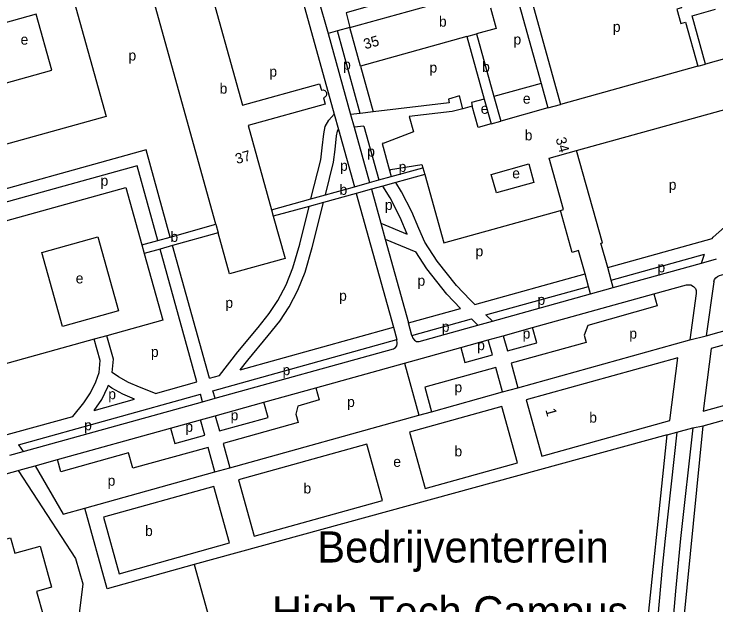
# Model space of a CAD drawing. Extents: x 158358 to 160383, y 379531 to 380764.
# Drawn here: x 159753.6 to 160024.2, y 380106.3 to 380334.2 of the extents above; entities that cross this region are included whole.
import ezdxf

# ---------------------------------------------------------------- set-up
doc = ezdxf.new("R2010")
doc.units = 0
for name, color, linetype in [('BLT_Basislijn', 7, 'Continuous'), ('BLT_Bebouwing', 7, 'Continuous'), ('BLT_Centroide', 7, 'Continuous'), ('BLT_Huisnummer', 7, 'Continuous'), ('BLT_Huisnummer_reeks', 7, 'Continuous'), ('BLT_Onderverdeling_panden', 7, 'Continuous'), ('BLT_Sport_parknaam', 7, 'Continuous')]:
    doc.layers.add(name, color=color, linetype=linetype)

msp = doc.modelspace()

# ---------------------------------------------------------------- linework, layer by layer
at = {"layer": 'BLT_Basislijn'}
for p, q in [((159931.55, 380417.09), (159964.23, 380299.3)), ((159943.9, 380353.87), (159956.78, 380307.42)), ((159887.16, 380314.11), (159892.07, 380296.44)), ((159956.78, 380307.42), (159959.41, 380297.96)), ((159898.37, 380273.85), (159899.01, 380271.52)), ((159894.97, 380253.48), (159905.09, 380249.26)), ((159896.67, 380247.35), (159908.43, 380242.45)), ((159982.44, 380236.4), (160022.76, 380247.6)), ((159983.78, 380231.58), (160019.71, 380241.57)), ((159931.28, 380222.18), (159973.73, 380233.97)), ((159935.51, 380218.16), (159975.06, 380229.16)), ((159953.5, 380213.3), (160000.19, 380226.28)), ((159905.65, 380215.05), (159925.68, 380220.62)), ((159906.99, 380210.23), (159905.65, 380215.05)), ((159906.99, 380210.23), (159929.89, 380216.6)), ((159840.8, 380197.03), (159899.87, 380213.45)), ((159899.87, 380213.45), (159901.21, 380208.63)), ((159942.17, 380210.15), (159953.5, 380213.3)), ((159942.17, 380210.15), (159943.82, 380204.33)), ((160014.1, 380208.5), (160020.43, 380210.12)), ((159830.24, 380188.9), (159901.21, 380208.63)), ((159925.81, 380205.6), (159936.4, 380208.55)), ((159937.99, 380202.72), (159936.4, 380208.55)), ((159904.12, 380199.58), (159925.81, 380205.6)), ((159869.86, 380190.05), (159904.12, 380199.58)), ((159904.12, 380199.58), (159909.69, 380179.49)), ((159945.19, 380199.52), (159947.86, 380190.08)), ((159939.31, 380197.89), (159911.89, 380190.28)), ((159941.9, 380188.45), (159939.31, 380197.89)), ((159828.91, 380193.72), (159832.72, 380194.78)), ((159808.05, 380187.92), (159824.09, 380192.38)), ((159849.91, 380184.51), (159869.86, 380190.05)), ((159911.89, 380190.28), (159914.51, 380180.83)), ((159941.9, 380188.45), (159947.86, 380190.08)), ((159755.26, 380168.06), (159825.43, 380187.56)), ((159914.51, 380180.83), (159941.9, 380188.45)), ((159784.47, 380181.37), (159799.95, 380185.67)), ((159831.17, 380179.3), (159849.91, 380184.51)), ((159831.17, 380179.3), (159832.81, 380173.46)), ((159836.8, 380159.21), (159909.69, 380179.49)), ((159909.69, 380179.49), (159914.51, 380180.83)), ((159700.92, 380158.15), (159776.17, 380179.06)), ((159813.89, 380174.49), (159825.45, 380177.71)), ((159827.08, 380171.84), (159825.45, 380177.71)), ((159770.26, 380162.37), (159813.89, 380174.49)), ((160009.06, 380172.98), (160015.33, 380174.69)), ((160015.33, 380174.69), (160019.2, 380175.38)), ((160005.42, 380171.89), (160009.06, 380172.98)), ((159834.16, 380168.65), (159836.8, 380159.21)), ((159755.26, 380168.06), (159757.09, 380165.46)), ((159831.02, 380157.61), (159828.41, 380167.02)), ((159761.71, 380159.99), (159770.26, 380162.37)), ((159831.02, 380157.61), (159836.8, 380159.21))]:
    msp.add_line(p, q, dxfattribs=at)
for points in [[(159894.88, 380347.44), (159897.28, 380339.12), (159881.55, 380334.6), (159883.03, 380328.99)], [(159864.4, 380341.04), (159877.04, 380295.57)], [(159870.73, 380340.69), (159874.63, 380326.66)], [(159883.03, 380328.99), (159878.21, 380327.65)], [(159878.21, 380327.65), (159874.63, 380326.66)], [(159874.63, 380326.66), (159883.32, 380295.38)], [(159887.05, 380295.83), (159878.21, 380327.65)], [(159956.78, 380307.42), (159938.6, 380302.42)], [(159926.61, 380297.67), (159925.35, 380302.58), (159921.12, 380301.39), (159921.36, 380299.97), (159892.07, 380296.44)], [(159934.86, 380301.39), (159929.88, 380300.02), (159930.25, 380298.67)], [(159868.05, 380262.93), (159871.79, 380277.92), (159872.4, 380282.55), (159872.96, 380288.04), (159873.57, 380290.78), (159874.93, 380293.24), (159877.04, 380295.57)], [(159877.04, 380295.57), (159878.68, 380289.68)], [(159887.05, 380295.83), (159883.32, 380295.38)], [(159892.07, 380296.44), (159887.05, 380295.83)], [(159883.32, 380295.38), (159884.68, 380290.51)], [(159888.45, 380290.96), (159884.68, 380290.51)], [(159884.68, 380290.51), (159890.6, 380269.19)], [(159888.45, 380290.96), (159894.2, 380270.18)], [(159873.59, 380264.47), (159876.71, 380276.99), (159877.37, 380281.97), (159877.9, 380287.23), (159878.3, 380288.99), (159878.68, 380289.68)], [(159878.68, 380289.68), (159884.82, 380267.58)], [(160022.76, 380247.6), (160023.14, 380248.08), (160029.71, 380253.93), (160036.19, 380260.62), (160054.43, 380283.44)], [(159813.81, 380248.2), (159804.49, 380281.82), (159728.62, 380260.79)], [(159982.44, 380236.4), (159979.84, 380245.78), (159980.38, 380245.93), (159970.47, 380281.52)], [(159809, 380246.85), (159801.01, 380275.67), (159729.96, 380255.97)], [(159931.28, 380222.18), (159929.36, 380224), (159924.16, 380229.47), (159916.72, 380238.89), (159911.99, 380246.15), (159909.59, 380251.47), (159906.97, 380257.87), (159902.92, 380265.67), (159900.8, 380269.23)], [(159891.32, 380266.62), (159894.97, 380253.48)], [(159905.09, 380249.26), (159902.43, 380255.77), (159898.54, 380263.24), (159895.81, 380267.86)], [(159885.53, 380265.03), (159899.87, 380213.45)], [(159840.8, 380197.03), (159843.71, 380200.77), (159851.51, 380210.18), (159856.03, 380215.77), (159859.6, 380221.24), (159862.98, 380227.71), (159865.79, 380234.65), (159868.53, 380244.18), (159872.86, 380261.54)], [(159832.72, 380194.78), (159839.81, 380203.9), (159847.64, 380213.35), (159851.99, 380218.72), (159855.28, 380223.77), (159858.44, 380229.81), (159861.05, 380236.28), (159863.7, 380245.48), (159867.33, 380260.02)], [(159973.73, 380233.97), (159971.23, 380242.96), (159968.71, 380242.26), (159964.23, 380258.45)], [(159894.97, 380253.48), (159896.67, 380247.35)], [(159896.67, 380247.35), (159905.65, 380215.05)], [(159828.91, 380193.72), (159814.72, 380244.92)], [(159824.09, 380192.38), (159809.91, 380243.57)], [(159925.68, 380220.62), (159920.38, 380226.19), (159912.66, 380235.97), (159908.43, 380242.45)], [(160018.59, 380238.14), (160019.71, 380241.57)], [(160018.59, 380238.14), (160024.38, 380239.75)], [(159983.78, 380231.58), (159982.44, 380236.4)], [(159984.58, 380228.69), (160018.59, 380238.14)], [(159975.06, 380229.16), (159973.73, 380233.97)], [(160023.36, 380230.91), (160023.63, 380231.76), (160024.09, 380232.43), (160024.73, 380232.98), (160025.52, 380233.33), (160029.14, 380234.33)], [(159984.58, 380228.69), (159983.78, 380231.58)], [(160023.36, 380230.91), (160020.43, 380210.12)], [(159975.87, 380226.27), (159975.06, 380229.16)], [(159975.87, 380226.27), (159984.58, 380228.69)], [(160000.19, 380226.28), (160012.79, 380229.78), (160014.47, 380229.82), (160015.59, 380229.13), (160016.28, 380228.29), (160016.55, 380227.52), (160016.55, 380226.41)], [(159938.05, 380215.75), (159975.87, 380226.27)], [(160000.19, 380226.28), (160001.47, 380221.65), (159974.82, 380214.12), (159973.35, 380210.4), (159974.15, 380207.57), (159945.19, 380199.52)], [(160016.55, 380226.41), (160014.1, 380208.5)], [(160020.43, 380210.12), (160058.15, 380220.73)], [(159938.05, 380215.75), (159935.51, 380218.16)], [(159932.43, 380214.19), (159929.89, 380216.6)], [(159932.43, 380214.19), (159938.05, 380215.75)], [(159906.99, 380210.23), (159907.37, 380209.23), (159907.91, 380208.44), (159908.77, 380207.95), (159909.7, 380207.87), (159932.43, 380214.19)], [(159943.82, 380204.33), (159955.1, 380207.46), (159953.5, 380213.3)], [(159791.36, 380195.9), (159791.87, 380201.04), (159789.32, 380210.16)], [(159936.4, 380208.55), (159942.17, 380210.15)], [(159776.17, 380179.06), (159780.44, 380184.33), (159783.03, 380188.11), (159785.07, 380192.34), (159786.35, 380195.97), (159786.8, 380200.6), (159784.5, 380208.82)], [(159831.05, 380186.01), (159899.89, 380205.15), (159900.67, 380205.65), (159901.09, 380206.24), (159901.32, 380207.11), (159901.21, 380208.63)], [(159947.86, 380190.08), (160014.1, 380208.5)], [(159925.81, 380205.6), (159927.42, 380199.78), (159937.99, 380202.72)], [(159808.05, 380187.92), (159801.94, 380190.26), (159797.73, 380192.05), (159793.9, 380194.25), (159791.36, 380195.9)], [(159784.47, 380181.37), (159787.37, 380185.6), (159789.69, 380190.42), (159789.87, 380190.91)], [(159799.95, 380185.67), (159795.5, 380187.56), (159791.29, 380189.98), (159789.87, 380190.91)], [(159869.86, 380190.05), (159871.15, 380185.39), (159862.98, 380183), (159862.27, 380179.89), (159863.15, 380176.71), (159834.16, 380168.65)], [(160019.2, 380175.38), (160073.01, 380190.33)], [(159826.23, 380184.67), (159825.43, 380187.56)], [(159831.05, 380186.01), (159830.24, 380188.9)], [(159757.09, 380165.46), (159826.23, 380184.67)], [(159826.23, 380184.67), (159831.05, 380186.01)], [(159832.81, 380173.46), (159851.53, 380178.67), (159849.91, 380184.51)], [(159825.45, 380177.71), (159831.17, 380179.3)], [(159813.89, 380174.49), (159815.5, 380168.65), (159827.08, 380171.84)], [(160015.33, 380174.69), (160010.57, 380131.9), (160008.55, 380111.65), (160007.13, 380095.3)], [(160010.67, 380088.45), (160019.2, 380175.38)], [(160005.42, 380171.89), (159823.01, 380121.88)], [(159996.53, 380086.65), (160005.42, 380171.89)], [(160009.06, 380172.98), (160004.59, 380131.94), (160003.46, 380120.81), (160001.19, 380094.85)], [(159828.41, 380167.02), (159799.39, 380159.02), (159797.74, 380165.02), (159771.55, 380157.68), (159770.26, 380162.37)], [(159751.98, 380164.03), (159757.09, 380165.46)], [(159725.52, 380149.93), (159755.15, 380158.17)], [(159755.15, 380158.17), (159755.48, 380158.26), (159758.37, 380159.06), (159761.71, 380159.99)], [(159755.15, 380158.17), (159777.32, 380124.26), (159780.09, 380114.47), (159775.39, 380076.25)], [(159761.71, 380159.99), (159772.55, 380141.36), (159780.81, 380143.65)], [(159780.81, 380143.65), (159831.02, 380157.61)], [(159823.01, 380121.88), (159789.45, 380112.55), (159780.81, 380143.65)], [(159823.01, 380121.88), (159836.22, 380074.34), (159815.03, 380068.45)]]:
    msp.add_lwpolyline(points, dxfattribs=at)
at = {"layer": 'BLT_Bebouwing'}
for p, q in [((159937.28, 380336.53), (159939.47, 380328.65)), ((159928.17, 380325.51), (159934.86, 380301.39)), ((159931.91, 380326.55), (159938.6, 380302.42)), ((159934.86, 380301.39), (159937.5, 380291.86)), ((159938.6, 380302.42), (159941.24, 380292.9)), ((159959.41, 380297.96), (159964.23, 380299.3)), ((159899.01, 380271.52), (159911.18, 380274.89)), ((159894.2, 380270.18), (159899.01, 380271.52)), ((159911.9, 380272.29), (159900.8, 380269.23)), ((159884.82, 380267.58), (159890.6, 380269.19)), ((159890.6, 380269.19), (159894.2, 380270.18)), ((159900.8, 380269.23), (159895.81, 380267.86)), ((159873.59, 380264.47), (159884.82, 380267.58)), ((159891.32, 380266.62), (159885.53, 380265.03)), ((159895.81, 380267.86), (159891.32, 380266.62)), ((159868.05, 380262.93), (159873.59, 380264.47)), ((159885.53, 380265.03), (159872.86, 380261.54)), ((159852.83, 380258.71), (159868.05, 380262.93)), ((159872.86, 380261.54), (159867.33, 380260.02)), ((159867.33, 380260.02), (159853.52, 380256.22)), ((159813.81, 380248.2), (159831.33, 380253.11)), ((159832.24, 380249.83), (159814.72, 380244.92)), ((159802.81, 380245.12), (159809, 380246.85)), ((159809, 380246.85), (159813.81, 380248.2)), ((159814.72, 380244.92), (159809.91, 380243.57)), ((159809.91, 380243.57), (159803.73, 380241.84))]:
    msp.add_line(p, q, dxfattribs=at)
for points in [[(159815.22, 380346.91), (159827.42, 380350.28), (159841.63, 380299.07), (159871.39, 380307.31), (159872.07, 380304.87), (159872.74, 380304.9), (159873.33, 380304.67), (159873.74, 380304.29), (159873.99, 380303.78), (159874.03, 380303.11), (159873.84, 380302.58), (159873.44, 380302.12), (159872.91, 380301.85), (159873.51, 380299.39), (159843.83, 380291.16), (159852.83, 380258.71)], [(160007.88, 380347.68), (160010.96, 380336.55), (160009.16, 380336.05), (160010.67, 380330.52), (160012.49, 380331.02), (160017.17, 380314.03)], [(159831.33, 380253.11), (159806, 380344.38), (159811.38, 380345.86)], [(159775.8, 380342.21), (159789.03, 380294.66), (159701.07, 380270.2)], [(159883.03, 380328.99), (159924.03, 380340.42)], [(159740.39, 380328.03), (159746.38, 380306.45), (159768.09, 380312.47), (159762.1, 380334.06), (159740.39, 380328.03)], [(160020.18, 380314.87), (160015.02, 380333.53), (160024, 380336.04)], [(159887.16, 380314.11), (159883.03, 380328.99)], [(159939.47, 380328.65), (159931.91, 380326.55)], [(159928.17, 380325.51), (159887.16, 380314.11)], [(159970.47, 380281.52), (160055.47, 380305.1), (160053.61, 380311.8), (160053.36, 380311.73), (160052.69, 380314.13), (160052.94, 380314.2), (160050.41, 380323.28)], [(160050.41, 380323.28), (160020.18, 380314.87)], [(160017.17, 380314.03), (159964.23, 380299.3)], [(159930.25, 380298.67), (159926.61, 380297.67)], [(159937.5, 380291.86), (159932.53, 380290.48), (159930.25, 380298.67)], [(159926.61, 380297.67), (159922.54, 380296.56), (159905.89, 380294.63), (159907.54, 380288.74), (159895.88, 380284.23), (159895.85, 380284.33), (159895.5, 380284.23), (159898.37, 380273.85)], [(159959.41, 380297.96), (159941.24, 380292.9)], [(159964.23, 380258.45), (159965.38, 380258.77), (159959.89, 380278.59), (159970.47, 380281.52)], [(159898.37, 380273.85), (159898.73, 380273.95), (159898.66, 380274.18), (159910.83, 380276.14)], [(159910.83, 380276.14), (159911.18, 380274.89)], [(159939.56, 380265.21), (159937.57, 380272.36), (159952.01, 380276.37), (159954, 380269.22), (159939.56, 380265.21)], [(159911.9, 380272.29), (159919.22, 380245.91), (159964.23, 380258.45)], [(159731.8, 380249.35), (159796.63, 380267.34)], [(159796.63, 380267.34), (159802.81, 380245.12)], [(159853.52, 380256.22), (159858.05, 380239.91)], [(159836.65, 380233.94), (159832.24, 380249.83)], [(159772.19, 380213.71), (159764.26, 380242.28), (159785.9, 380248.28), (159793.82, 380219.71), (159772.19, 380213.71)], [(159803.73, 380241.84), (159810.88, 380216.14)], [(159858.05, 380239.91), (159836.65, 380233.94)], [(159810.88, 380216.14), (159789.32, 380210.16)], [(160022.32, 380205.25), (160019.31, 380181.02), (160063.8, 380193.36), (160057.76, 380215.1), (160022.32, 380205.25)], [(159789.32, 380210.16), (159784.5, 380208.82)], [(159784.5, 380208.82), (159693.83, 380183.67)], [(160009.44, 380201.67), (159951.07, 380185.46)], [(159951.07, 380185.46), (159957.11, 380163.73), (160006.42, 380177.43), (160009.44, 380201.67)], [(159941.58, 380182.81), (159905.98, 380172.93)], [(159905.98, 380172.93), (159912.02, 380151.2), (159947.62, 380161.09), (159941.58, 380182.81)], [(159889.55, 380168.36), (159840.08, 380154.62)], [(159840.08, 380154.62), (159846.12, 380132.88), (159895.59, 380146.62), (159889.55, 380168.36)], [(159830.59, 380151.97), (159788.06, 380140.16), (159794.11, 380118.39), (159836.63, 380130.24), (159830.59, 380151.97)], [(159732.18, 380126.53), (159752.18, 380132.19), (159753.81, 380126.29), (159763.63, 380129.02), (159768.01, 380113.16), (159762.28, 380111.58), (159764.96, 380101.97)]]:
    msp.add_lwpolyline(points, dxfattribs=at)
at = {"layer": 'BLT_Onderverdeling_panden'}
for p, q in [((159928.17, 380325.51), (159931.91, 380326.55)), ((160017.17, 380314.03), (160020.18, 380314.87)), ((159937.5, 380291.86), (159941.24, 380292.9)), ((159911.18, 380274.89), (159911.9, 380272.29)), ((159852.83, 380258.71), (159853.52, 380256.22)), ((159831.33, 380253.11), (159832.24, 380249.83)), ((159802.81, 380245.12), (159803.73, 380241.84))]:
    msp.add_line(p, q, dxfattribs=at)

# ---------------------------------------------------------------- texts
at = {"layer": 'BLT_Centroide'}
for s, p in [('b', (159917.38, 380329.28)), ('p', (159984.43, 380327.28)), ('e', (159756.08, 380322.35)), ('p', (159946.12, 380322.42)), ('p', (159797.68, 380316.24)), ('p', (159880.43, 380312.7)), ('p', (159913.73, 380311.57)), ('b', (159934.03, 380311.82)), ('p', (159852, 380310.02)), ('b', (159832.83, 380303.47)), ('e', (159949.74, 380299.59)), ('e', (159933.51, 380295.7)), ('b', (159950.45, 380285.45)), ('p', (159889.73, 380279.2)), ('p', (159879.25, 380273.73)), ('p', (159901.84, 380273.31)), ('e', (159945.64, 380270.8)), ('p', (159786.92, 380267.95)), ('b', (159879.06, 380264.47)), ('p', (160005.97, 380266.4)), ('p', (159896.53, 380258.63)), ('b', (159813.85, 380246.32)), ('p', (159931.49, 380240.77)), ('p', (160001.62, 380234.56)), ('e', (159777.35, 380230.31)), ('p', (159909.11, 380229.41)), ('p', (159878.88, 380223.62)), ('p', (159955.36, 380222.03)), ('p', (159835.04, 380220.88)), ('p', (159918.46, 380211.67)), ('p', (159949.65, 380209.02)), ('p', (159990.79, 380209.02)), ('p', (159932.11, 380204.56)), ('p', (159806.33, 380201.94)), ('p', (159857.1, 380194.94)), ('p', (159923.37, 380188.32)), ('p', (159789.9, 380185.67)), ('p', (159881.97, 380182.66)), ('p', (159837.07, 380177.52)), ('b', (159975.33, 380176.66)), ('p', (159780.59, 380173.68)), ('p', (159819.61, 380173.1)), ('b', (159923.36, 380163.63)), ('e', (159899.78, 380159.59)), ('p', (159789.64, 380152.29)), ('b', (159865.14, 380149.34)), ('b', (159804.07, 380132.91))]:
    msp.add_text(s, height=4, dxfattribs=at).set_placement(p)
at = {"layer": 'BLT_Huisnummer'}
msp.add_text('1', height=4, rotation=285.5322, dxfattribs=at).set_placement((159958.38, 380181.6))
at = {"layer": 'BLT_Huisnummer_reeks'}
for s, rotation, p in [('35', 15.5337, (159888.93, 380320.54)), ('34', 285.5114, (159962.33, 380286.12)), ('37', 15.6089, (159839.47, 380276.29))]:
    msp.add_text(s, height=4, rotation=rotation, dxfattribs=at).set_placement(p)
at = {"layer": 'BLT_Sport_parknaam'}
for s, p in [('Bedrijventerrein', (159870.48, 380122.7)), ('High Tech Campus', (159853.03, 380097.7))]:
    msp.add_text(s, height=12, dxfattribs=at).set_placement(p)

doc.saveas('drawing.dxf')
